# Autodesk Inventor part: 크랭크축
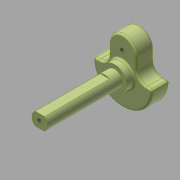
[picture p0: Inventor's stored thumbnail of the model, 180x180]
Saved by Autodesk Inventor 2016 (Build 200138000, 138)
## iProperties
Created: 2018-01
Part Number: 크랭크축
Material: 강철, 탄소
Document SubType Name: Modeling
Designer: mduedu
Density: 7.87 g/cm^3
Appearance: 아연 크롬산색 2
Mass: 57.3416 g
Surface Area: 32.1344 cm^2
Volume: 7.2861 cm^3
Author: mduedu
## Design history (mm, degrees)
sketch "스케치1"
  geometry: L1 (-15, 0)-(15, 0); L2 (-7, 0)-(7, 0); L3 (7, 0)-(7, 10); L4 (-7, 10)-(-7, 0); A1 r 15 centre (0, 0) between (-15, 0) and (15, 0); A2 r 7 centre (0, 10) between (7, 10) and (-7, 10); 3 further points
  constraints: 8 end point, 4 point on circle, 3 coincident, 2 centre point, 2 horizontal, 2 midpoint, 2 tangent, 1 parallel, 1 perpendicular, 1 point on line
  dimensions: "d0" = 30 diameter of A1; "d1" = 17 dimension on A2 L1; "d2" = 7 radius of A2
extrude "돌출1" new body sketch "스케치1" distance "d4" = 9; taper "d5" = 0 deg
sketch "스케치2"
  geometry: C1 r 6 at (0, 0); 1 further point
  constraints: 1 centre point, 1 coincident
  dimensions: "d6" = 12 diameter of C1
extrude "돌출2" join sketch "스케치2" distance "d7" = 4; taper "d8" = 0 deg
sketch "스케치3"
  geometry: C1 r 4 at (0, 0); 1 further point
  constraints: 1 centre point, 1 coincident
  dimensions: "d9" = 8 diameter of C1
extrude "돌출3" join sketch "스케치3" distance "d10" = 38; taper "d11" = 0 deg
sketch "스케치4"
  geometry: L1 (-2.332, 3.25)-(2.332, 3.25); L2 (-2.332, -3.25)-(2.332, -3.25); A1 r 4 centre (0, 0) between (-2.332, 3.25) and (2.332, 3.25) reference; A2 r 4 centre (0, 0) between (2.332, 3.25) and (-2.332, 3.25); A3 r 4 centre (0, 0) between (-2.332, -3.25) and (2.332, -3.25); 1 further point
  constraints: 8 point on circle, 4 end point, 2 centre point, 2 coincident, 2 parallel, 1 horizontal
  dimensions: "d12" = 6.5 distance between parallel lines of L2 L1
extrude "돌출4" cut sketch "스케치4" distance "d13" = 33; taper "d14" = 0 deg
fillet "모깎기1" dims "d15" = 5
fillet "모깎기2" dims "d16" = 1
fillet "모깎기3" dims "d17" = 1
fillet "모깎기4" dims "d18" = 1
sketch "스케치5"
  geometry: 1 further point
  constraints: 1 other
hole "구멍1" sketch "스케치5" at (0, 10) diameter "d19" = 2.459; stored, may be unused: countersink angle "d23" = 90 deg, drill point angle "d25" = 120 deg; dims "d20" = 10, "d21" = 4, "d22" = 2, "d24" = 11.5
sketch "스케치6"
  geometry: 1 further point
  constraints: 1 other
hole "구멍2" sketch "스케치6" at (0, 0) diameter "d26" = 2.459; stored, may be unused: countersink angle "d30" = 90 deg, drill point angle "d32" = 120 deg; dims "d27" = 12.7, "d28" = 4, "d29" = 2, "d31" = 14.2
node "솔리드1"
node "투영된 루프1"
